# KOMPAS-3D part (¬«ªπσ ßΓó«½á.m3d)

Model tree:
1. Эскиз:5
2. Операция выдавливания:3
     Расстояние 1 = 10; Угол 1 = 10; Расстояние 2 = 40; Угол 2 = 41
3. Эскиз:6
4. Вырезать элемент выдавливания:4
     Расстояние 2 = 43.1215; Расстояние 1 = 43.1215
5. Эскиз:7
6. Вырезать элемент выдавливания:5
     Расстояние 1 = 34.2699
7. Скругление:6
     Радиус = 4
8. Скругление:7
     Радиус = 2
9. Эскиз:8
10. Вырезать элемент выдавливания:6
     Угол 2 = 4; Расстояние 1 = 34.2699; Угол 1 = 9
11. Эскиз:9
12. Операция выдавливания:4
     Расстояние 1 = 0.3; Расстояние 2 = 0.5
13. Скругление:8
     Радиус = 2.5

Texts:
  stalker61
  Кожа техническая  ГОСТ 20836-75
